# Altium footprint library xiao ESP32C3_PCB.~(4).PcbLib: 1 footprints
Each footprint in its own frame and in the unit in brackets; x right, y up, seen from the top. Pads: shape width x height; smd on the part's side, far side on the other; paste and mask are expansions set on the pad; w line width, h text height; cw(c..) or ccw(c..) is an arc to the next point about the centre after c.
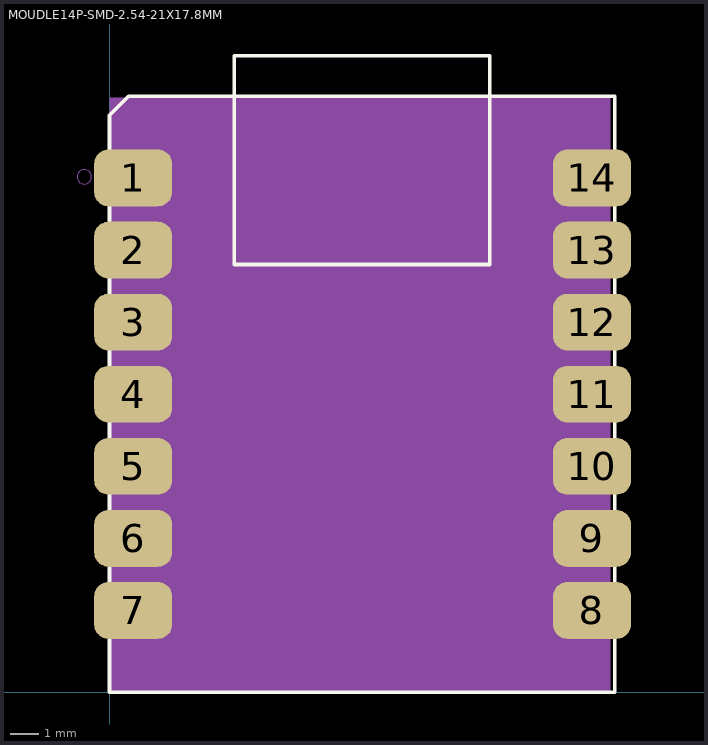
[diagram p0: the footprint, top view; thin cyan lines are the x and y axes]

## MOUDLE14P-SMD-2.54-21X17.8MM [mm]
pads (14):
  rrect50% 2.75x2 smd: 1(0.835,18.12) 2(0.835,15.58) 3(0.835,13.04) 4(0.835,10.5) 5(0.835,7.96) 6(0.835,5.42) 7(0.835,2.88) 8(17,2.88) 9(17,5.42) 10(17,7.96) 11(17,10.5) 12(17,13.04) 13(17,15.58) 14(17,18.12)
F.SilkS:
  lines w0.127: 4.396,22.425 4.396,15.072 13.395,15.072 13.395,22.424 4.4,22.424 ; 0,0 0,20.328 0.672,21 17.8,21 17.8,0 0,0
Dwgs.User:
  circle w0: c-0.889,18.161 r0.254
F.CrtYd:
  region: 17.653,0 0,0 0,20.955 17.653,20.955
3D body "Seeed Studio XIAO-ESP32-C3.step": height 4.19, standoff -0.02, extent 0,0 17.78,22.463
